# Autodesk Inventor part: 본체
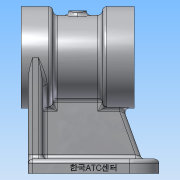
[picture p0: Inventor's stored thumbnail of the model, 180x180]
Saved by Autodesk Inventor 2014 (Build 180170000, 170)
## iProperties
Created: 2020-06
Part Number: 본체
Material: 알루미늄 6061
Document SubType Name: Modeling
Designer: NET
Density: 2.71 g/cm^3
Appearance: 알루미늄 - 평지
Mass: 727.735 g
Surface Area: 642.521 cm^2
Volume: 268.537 cm^3
Author: NET
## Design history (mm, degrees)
sketch "스케치1"
  geometry: L1 (0, 0)-(78, 0); L2 (0, 0)-(0, 35); L3 (0, 35)-(22, 35); L4 (22, 35)-(22, 29); L5 (22, 29)-(56, 29); L6 (56, 29)-(56, 35); L7 (56, 35)-(78, 35); L8 (78, 35)-(78, 0)
  constraints: 16 end point, 4 perpendicular, 2 horizontal, 2 parallel
  dimensions: "d0" = 70 diameter of L3 L1; "d1" = 78 distance between parallel lines of L8 L2; "d2" = 22 distance between parallel lines of L2 L4; "d3" = 22 distance between parallel lines of L8 L6; "d4" = 70 diameter of L7 L1; "d5" = 58 diameter of L5 L1
revolve "회전1" sketch "스케치1" stored, may be unused: angle "d6" = 90 deg
node "작업 평면2"
sketch "스케치5"
  geometry: L1 (-49, -70)-(49, -70); L2 (49, -70)-(49, -80); L3 (49, -80)-(-49, -80); L4 (-49, -80)-(-49, -70); L5 (0, 0)-(0, -52.1)
  constraints: 10 end point, 3 parallel, 1 horizontal, 1 perpendicular, 1 other
  dimensions: "d26" = 10 distance between parallel lines of L1 L3; "d27" = 98 distance between parallel lines of L2 L4; "d28" = 80 distance from line of L3 L5.start
extrude "돌출2" join sketch "스케치5" distance "d29" = 90; taper "d30" = 0 deg
sketch "스케치6"
  geometry: L1 (-49, -70)-(49, -70) reference; L2 (49, -70)-(49, -80) reference; L3 (-35, 0)-(-35, -70); L4 (35, 0)-(35, -70); A1 r 35 centre (0, 0) between (-35, 0) and (35, 0) reference; 1 further point
  constraints: 4 end point, 2 point on circle, 2 point on line, 2 tangent, 1 parallel, 1 perpendicular
extrude "돌출3" join sketch "스케치6" distance "d31" = 10; taper "d32" = 0 deg
sketch "스케치7"
  geometry: L1 (5, -70)-(5, 0) reference; L2 (5, -70)-(95, -70) reference; L3 (56, -35)-(78, -35) reference; L4 (83, -70)-(70.261, -35); L5 (95, -80)-(95, -70) reference; L6 (22, -29)-(56, -29) reference; L7 (70.261, -35)-(66.105, -23.582); L8 (66.105, -23.582)-(5, -23.582); L9 (5, 0)-(5, -35) reference; 1 further point
  constraints: 6 end point, 3 point on line, 1 collinear, 1 parallel
  dimensions: "d33" = 70 deg angle of L2 L4; "d34" = 12 distance from line of L5 L4.start; "d35" = 5.41817 distance between parallel lines of L6 L8
extrude "돌출4" join sketch "스케치7" stored distance "d36" = 10; taper "d37" = 0 deg
sketch "스케치8"
  geometry: L1 (0, 0)-(78, 0); L2 (78, -35)-(78, 35) reference; L3 (0, 23.5)-(18, 23.5); L4 (18, 23.5)-(18, 20); L5 (18, 20)-(24, 20); L6 (24, 20)-(24, 23); L7 (24, 23)-(54, 23); L8 (22, -28.566)-(22, 29) reference; L9 (54, 23)-(54, 20); L10 (54, 20)-(60, 20); L11 (60, 20)-(60, 23.5); L12 (60, 23.5)-(78, 23.5); L13 (0, -35)-(0, 35) reference
  constraints: 20 end point, 5 perpendicular, 3 parallel, 2 point on line, 1 midpoint, 1 vertical
  dimensions: "d38" = 47 diameter of L3 L1; "d39" = 40 diameter of L5 L1; "d40" = 46 diameter of L7 L1; "d41" = 18 distance between parallel lines of L13 L4; "d42" = 6 distance between parallel lines of L6 L4; "d43" = 30 distance between parallel lines of L6 L9; "d44" = 40 diameter of L10 L1; "d45" = 47 diameter of L12 L1; "d46" = 18 distance between parallel lines of L2 L11
revolve "회전2" sketch "스케치8" stored, may be unused: angle "d47" = 90 deg
sketch "스케치9"
  geometry: C1 r 23.5 at (0, 0) reference; C2 r 35 at (0, 0) reference; A1 r 28.5 centre (0, 0) between (0, 28.5) and (28.5, 0); 2 further points
  constraints: 4 point on circle, 2 horizontal alignment, 2 vertical alignment, 1 centre point, 1 coincident
  dimensions: "d48" = 57 diameter of A1
hole "구멍1" sketch "스케치9" at (0, 28.5), (28.5, 0), (0, -28.5), (-28.5, 0) diameter "d49" = 3.242; stored, may be unused: countersink angle "d53" = 90 deg, drill point angle "d55" = 118 deg; dims "d50" = 10, "d51" = 4, "d52" = 2, "d54" = 12
node "작업 평면4"
node "작업 평면5"
sketch "스케치10"
  geometry: L1 (35, -39)-(-35, -39) reference; C1 r 6 at (0, 0); 1 further point
  constraints: 1 centre point, 1 vertical alignment
  dimensions: "d57" = 12 diameter of C1; "d58" = 39 distance from line of L1 C1.centre
extrude "돌출5" join sketch "스케치10" distance "d59" = 3; taper "d60" = 0 deg; dims "d61" = 1.5, "d62" = 0
hole "구멍2" diameter "d65" = 5.188; stored, may be unused: countersink angle "d69" = 90 deg, drill point angle "d71" = 0 deg; dims "d63" = 10, "d64" = 10, "d66" = 10, "d67" = 4, "d68" = 2, "d70" = 20
sketch "스케치11"
  geometry: L1 (98, -90)-(0, -90) reference; 5 further points
  constraints: 2 horizontal alignment, 2 vertical alignment
  dimensions: "d72" = 36 distance of point (20, -20) point (20, -56); "d73" = 58 distance of point (78, -20) point (20, -20); "d74" = 29 horizontal distance of point (20, -56) point (49, -95); "d75" = 70 distance from line of point (20, -20) L1
hole "구멍3" sketch "스케치11" at (20, -56), (20, -20), (78, -56), (78, -20) diameter "d76" = 9; stored, may be unused: countersink angle "d80" = 90 deg, drill point angle "d82" = 0 deg; dims "d77" = 10, "d78" = 4, "d79" = 2, "d81" = 20
sketch "스케치12"
  geometry: L1 (0, 0)-(10, 0) reference; L2 (10, 0)-(10, 90) reference; 2 further points
  constraints: 1 other
  dimensions: "d83" = 4 distance from line of L2 point (6, 45); "d84" = 45 distance from line of point (6, 45) L1
extrude "돌출6" join sketch "스케치12" distance "d85" = 0.5; taper "d86" = 0 deg
fillet "모깎기1" dims "d87" = 0.3
sketch "스케치13"
  geometry: L1 (98, -90)-(98, 0) reference; L2 (0, 0)-(98, 0) reference; L3 (0, -90)-(0, 0) reference; L4 (98, 0)-(0, 0) reference; C1 r 4.5 at (20, -20) reference; C2 r 4.5 at (78, -20) reference; A1 r 20 centre (20, -20) between (20, 0) and (0, -20); A2 r 20 centre (78, -20) between (98, -20) and (78, 0); 1 further point
  constraints: 4 point on circle, 4 point on line, 2 centre point, 2 coincident, 2 tangent
extrude "돌출7" cut sketch "스케치13" stored distance "d88" = 0.5; taper "d89" = 0 deg
fillet "모깎기2" dims "d90" = 3
fillet "모깎기3" dims "d91" = 3
fillet "모깎기4" dims "d92" = 3
fillet "모깎기5" dims "d93" = 3
fillet "모깎기6" dims "d94" = 3
fillet "모깎기7" dims "d95" = 3
chamfer "모따기1" distance "d96" = 1; stored, may be unused: second distance "d97" = 2, angle "d98" = 45 deg
chamfer "모따기2" distance "d99" = 1; stored, may be unused: second distance "d100" = 2, angle "d101" = 45 deg
fillet "모깎기8" dims "d102" = 3
sketch "스케치14"
  geometry: L1 (0, -76.178)-(58.375, -76.178); L2 (58.375, -76.178)-(58.375, 56.048); L3 (58.375, 56.048)-(0, 56.048); L4 (0, 56.048)-(0, -76.178); C1 r 1.621 at (28.5, 0) reference
  constraints: 8 end point, 2 parallel, 1 horizontal, 1 perpendicular
extrude "돌출8" cut sketch "스케치14" stored distance "d103" = 0; taper "d104" = 0 deg
node "솔리드1"
mirror "대칭1"
other parameters: "d25" = -5, "d56" = -39
